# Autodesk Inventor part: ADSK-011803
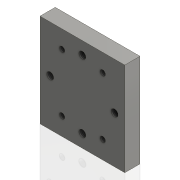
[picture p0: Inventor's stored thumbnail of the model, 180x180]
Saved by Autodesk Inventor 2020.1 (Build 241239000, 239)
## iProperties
Created: 2000-01
Part Number: ADSK-011803
Material: Aluminum
Description: LFL20SF BASE PLATE
Document SubType Name: Modeling
Designer: glanglot
Density: 2.71 g/cm^3
Appearance: Steel
Mass: 64.9577 g
Surface Area: 80.5079 cm^2
Volume: 23.9696 cm^3
Control State: 0
Checked Out: False
Master: False
Shininess: 0.0
Length Units: 11269
Angle Units: 11279
Time Units: 11290
Mass Units: 11283
Length Display Precision: 3
Angle Display Precision: 2
Compacted: True
Dimensions: 50x55x9 mm
Mass: 0,065 kg
Density: 0.0
Volumn: 0.0
Area: 0.0
PropertySet Name: Model Information
Author: glanglot
Revision Number: -
Title: LFL20SF BASE PLATE
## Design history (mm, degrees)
node "Solide1"
  node "Extrusion1" dims "d2" = 9 (= H3), "d3" = 0
  node "Hole1" dims "d10" = 4.134, "d11" = 4, "d12" = 2, "d13" = 60 deg, "d14" = 8, "d15" = 118 deg
  node "Hole2" dims "d24" = 3.242, "d25" = 4, "d26" = 2, "d27" = 60 deg, "d28" = 8, "d29" = 118 deg
sketch "Sketch1"
  geometry: L1 (0, 55)-(50, 55); L2 (50, 55)-(50, 0); L3 (50, 0)-(0, 0); L4 (0, 0)-(0, 55); 1 further point
  constraints: 8 end point, 2 parallel, 1 coincident, 1 horizontal, 1 perpendicular
  dimensions: "d0" = 55 distance of L3.end L1.start (= A); "d1" = 50 distance of L2.end L3.end (= C)
workplane "Work Plane3"
workplane "Work Plane1"
workplane "Work Plane2"
node "Corps solides"
node "Corps surfaciques"
sketch "Sketch2"
  geometry: L1 (0, 55)-(0, 0) reference; L2 (0, 0)-(50, 0) reference; L3 (50, 0)-(50, 55) reference; L4 (50, 55)-(0, 55) reference; L5 (25, 55)-(25, 0); L6 (0, 27.5)-(50, 27.5); 4 further points
  constraints: 4 end point, 4 midpoint, 4 point on line
  dimensions: "d4" = 20 distance from line of L6 point (25, 47.5) (= 0.5 x A1); "d5" = 20 distance from line of point (25, 7.5) L6 (= 0.5 x A1); "d8" = 19 distance from line of point (6, 27.5) L5 (= 0.5 x C3); "d9" = 19 distance from line of L5 point (44, 27.5) (= 0.5 x C3)
sketch "Sketch3"
  geometry: L1 (0, 55)-(0, 0) reference; L2 (0, 0)-(50, 0) reference; L3 (50, 0)-(50, 55) reference; L4 (50, 55)-(0, 55) reference; L5 (25, 55)-(25, 0); L6 (50, 27.5)-(0, 27.5); 4 further points
  constraints: 4 end point, 4 midpoint
  dimensions: "d16" = 12 distance from line of point (13, 44.5) L5 (= 0.5 x C2); "d17" = 12 distance from line of point (37, 44.5) L5 (= 0.5 x C2); "d18" = 12 distance from line of point (13, 10.5) L5 (= 0.5 x C2); "d19" = 12 distance from line of point (37, 10.5) L5 (= 0.5 x C2); "d20" = 17 distance from line of point (13, 44.5) L6 (= 0.5 x A2); "d21" = 17 distance from line of point (13, 10.5) L6 (= 0.5 x A2); "d22" = 17 distance from line of point (37, 10.5) L6 (= 0.5 x A2); "d23" = 17 distance from line of point (37, 44.5) L6 (= 0.5 x A2)
other parameters: "A" = 55 [user parameter; used in 2 equation terms], "C" = 50 [user parameter; used in 1 equation term], "C2" = 24 [user parameter; used in 4 equation terms], "C3" = 38 [user parameter; used in 2 equation terms], "C7" = 0 [user parameter], "A2" = 34 [user parameter; used in 4 equation terms], "A3" = 0 [user parameter], "H3" = 9 [user parameter; used in 1 equation term], "H4" = 0 [user parameter], "H2" = 13 [user parameter; used in 1 equation term], "H" = 22 [user parameter; used in 1 equation term], "d30" = -27.5 (= -0.5 x A), "d31" = -22 (= -H), "d32" = -13 (= -H2)
